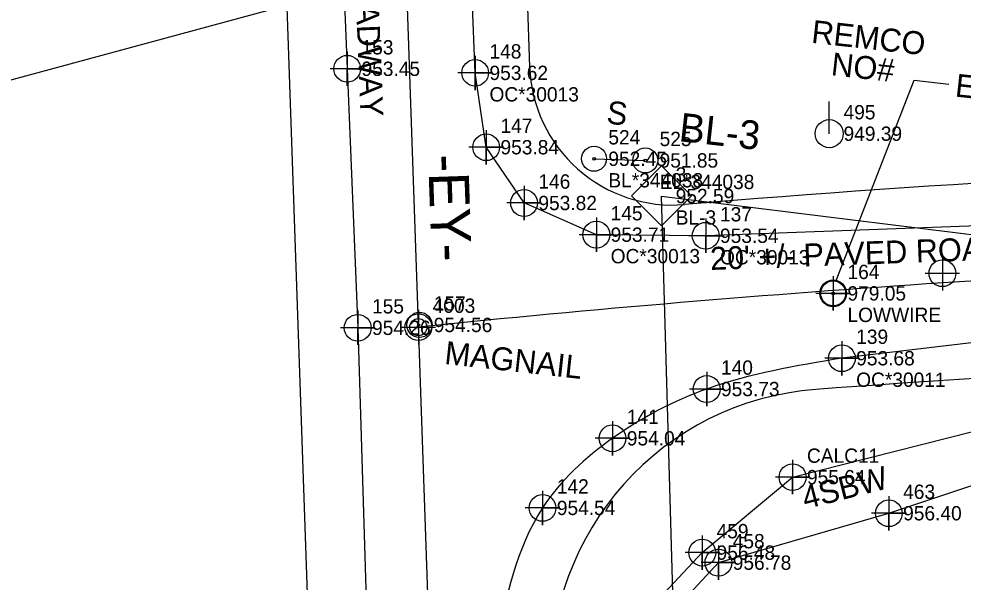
# Model space of a CAD drawing. Extents: x 1150279 to 1151282, y 654632 to 657999.
# Drawn here: x 1150502.6 to 1150667.5, y 657077.9 to 657176.2 of the extents above; entities that cross this region are included whole.
import ezdxf

# ---------------------------------------------------------------- set-up
doc = ezdxf.new("R2010")
doc.units = 0
for name, color, linetype in [('COGO Default Chain', 7, 'Continuous'), ('COGO Default Curve', 7, 'Continuous'), ('Cogo Default Point CELL', 7, 'Continuous'), ('COGO Default Point Number', 7, 'Continuous'), ('CTL Supplemental Horizontal and Vertical CELL', 7, 'Continuous'), ('CTL Supplemental Horizontal and Vertical Cogo Comment', 7, 'Continuous'), ('CTL Supplemental Horizontal and Vertical Cogo Elevation', 7, 'Continuous'), ('CTL Supplemental Horizontal and Vertical Cogo Number', 7, 'Continuous'), ('CTL Supplemental Horizontal and Vertical Text', 7, 'Continuous'), ('Default Symbol CELL', 7, 'Continuous'), ('Default Symbol Cogo Comment', 7, 'Continuous'), ('Default Symbol Cogo Elevation', 7, 'Continuous'), ('Default Symbol Cogo Number', 7, 'Continuous'), ('Exist Horizontal Alignment', 7, 'Continuous'), ('Exist Horizontal Alignment Direction Label', 7, 'Continuous'), ('Exist Horizontal Alignment Station Label', 7, 'Continuous'), ('Exist Other Culture Fence Line', 7, 'Continuous'), ('Exist Other Culture Fence Line Cogo Elevation', 7, 'Continuous'), ('Exist Other Culture Fence Line Cogo Number', 7, 'Continuous'), ('Exist Other Culture Fence Line Cogo Point CELL', 7, 'Continuous'), ('Exist Other Culture Fence Line Text', 7, 'Continuous'), ('Exist Other Culture Sign CELL', 7, 'Continuous'), ('Exist Other Culture Sign Cogo Comment', 7, 'Continuous'), ('Exist Other Culture Sign Cogo Elevation', 7, 'Continuous'), ('Exist Other Culture Sign Cogo Number', 7, 'Continuous'), ('Exist Other Culture Sign Text', 7, 'Continuous'), ('Exist Property Iron Pin CELL', 7, 'Continuous'), ('Exist Property Iron Pin Cogo Elevation', 7, 'Continuous'), ('Exist Property Iron Pin Cogo Number', 7, 'Continuous'), ('Exist Property Iron Pin Text', 7, 'Continuous'), ('Exist Property Line', 7, 'Continuous'), ('Exist Right of Way Line', 7, 'Continuous'), ('Exist Roads EOP', 7, 'Continuous'), ('Exist Roads EOP Cogo Comment', 7, 'Continuous'), ('Exist Roads EOP Cogo Elevation', 7, 'Continuous'), ('Exist Roads EOP Cogo Number', 7, 'Continuous'), ('Exist Roads EOP Cogo Point CELL', 7, 'Continuous'), ('Exist Roads EOP Text', 7, 'Continuous'), ('Exist Utilities Other Located Object CELL', 7, 'Continuous'), ('Exist Utilities Other Located Object Leader', 7, 'Continuous'), ('Exist Utilities Other Located Object Text', 7, 'Continuous'), ('Exist Utilities Power Pole CELL', 7, 'Continuous'), ('Exist Utilities Power Pole Cogo Elevation', 7, 'Continuous'), ('Exist Utilities Power Pole Cogo Number', 7, 'Continuous'), ('Exist Utilities Power Pole Text', 7, 'Continuous'), ('Old_Level_4', 7, 'Continuous')]:
    doc.layers.add(name, color=color, linetype=linetype)

msp = doc.modelspace()

# ---------------------------------------------------------------- linework, layer by layer
at = {"layer": 'COGO Default Chain'}
for p, q in [((1150568.54, 657231.15), (1150575.96, 657017.52)), ((1150663.4, 655450.47), (1150614.76, 657145.26)), ((1150614.76, 657145.26), (1150931.29, 657106.06))]:
    msp.add_line(p, q, dxfattribs=at)
msp.add_arc((1150828.33, 654635.5), 2500, 91.66254, 95.87761, dxfattribs=at)
at = {"layer": 'COGO Default Curve'}
msp.add_arc((1150828.33, 654635.5), 2500, 91.66254, 95.87761, dxfattribs=at)
at = {"layer": 'Cogo Default Point CELL'}
for points in [[(1150663.84, 657134.78), (1150663.84, 657131.78)], [(1150660.84, 657131.78), (1150663.84, 657131.78)], [(1150663.84, 657131.78), (1150666.84, 657131.78)], [(1150663.84, 657131.78), (1150663.84, 657128.78)], [(1150572.32, 657125.36), (1150572.32, 657122.36)], [(1150572.32, 657125.36), (1150572.32, 657122.36)], [(1150569.32, 657122.36), (1150572.32, 657122.36)], [(1150569.32, 657122.36), (1150572.32, 657122.36)], [(1150572.32, 657122.36), (1150575.32, 657122.36)], [(1150572.32, 657122.36), (1150572.32, 657119.36)], [(1150572.32, 657122.36), (1150575.32, 657122.36)], [(1150572.32, 657122.36), (1150572.32, 657119.36)]]:
    msp.add_lwpolyline(points, dxfattribs=at)
for centre in [(1150663.84, 657131.78), (1150572.32, 657122.36), (1150572.32, 657122.36)]:
    msp.add_circle(centre, 2.34, dxfattribs=at)
at = {"layer": 'CTL Supplemental Horizontal and Vertical CELL'}
msp.add_line((1150614.76, 657145.26), (1150614.76, 657145.26), dxfattribs=at)
msp.add_lwpolyline([(1150609.54, 657145.28), (1150614.78, 657150.52), (1150620.03, 657145.27), (1150614.79, 657140.03)], close=True, dxfattribs=at)
at = {"layer": 'Default Symbol CELL'}
msp.add_lwpolyline([(1150644.76, 657131.26), (1150644.76, 657125.26), (1150644.76, 657128.26), (1150647.76, 657128.26), (1150641.76, 657128.26)], dxfattribs=at)
msp.add_circle((1150644.76, 657128.26), 2.34, dxfattribs=at)
at = {"layer": 'Exist Horizontal Alignment'}
msp.add_line((1150568.54, 657231.15), (1150575.96, 657017.52), dxfattribs=at)
msp.add_arc((1150828.33, 654635.5), 2500, 91.66254, 95.87761, dxfattribs=at)
at = {"layer": 'Exist Horizontal Alignment Station Label'}
msp.add_circle((1150572.32, 657122.36), 1.5, dxfattribs=at)
at = {"layer": 'Exist Other Culture Fence Line'}
for points in [[(1150601.9, 657018.95), (1150605.15, 657042.83), (1150611.98, 657072.42), (1150621.9, 657083), (1150637.68, 657096.18), (1150678.11, 657106.44)], [(1150604.36, 657025.64), (1150606.72, 657040.79), (1150614.66, 657070.42), (1150624.72, 657081.25), (1150654.48, 657089.88), (1150677.88, 657097.66), (1150678.26, 657106.74)]]:
    msp.add_lwpolyline(points, dxfattribs=at)
at = {"layer": 'Exist Other Culture Fence Line Cogo Point CELL'}
for points in [[(1150637.68, 657099.18), (1150637.68, 657093.18), (1150637.68, 657096.18), (1150640.68, 657096.18), (1150634.68, 657096.18)], [(1150654.48, 657092.88), (1150654.48, 657086.88), (1150654.48, 657089.88), (1150657.48, 657089.88), (1150651.48, 657089.88)], [(1150621.9, 657086), (1150621.9, 657080), (1150621.9, 657083), (1150624.9, 657083), (1150618.9, 657083)], [(1150624.72, 657084.25), (1150624.72, 657078.25), (1150624.72, 657081.25), (1150627.72, 657081.25), (1150621.72, 657081.25)]]:
    msp.add_lwpolyline(points, dxfattribs=at)
for centre in [(1150637.68, 657096.18), (1150654.48, 657089.88), (1150621.9, 657083), (1150624.72, 657081.25)]:
    msp.add_circle(centre, 2.34, dxfattribs=at)
at = {"layer": 'Exist Other Culture Sign CELL'}
for centre, radius in [((1150603, 657151.76), 2.18), ((1150611.95, 657151.47), 2.18), ((1150603, 657151.76), 0.24), ((1150611.95, 657151.47), 0.24)]:
    msp.add_circle(centre, radius, dxfattribs=at)
at = {"layer": 'Exist Property Iron Pin CELL'}
for radius in [2.2, 0.0707]:
    msp.add_circle((1150572.51, 657122.75), radius, dxfattribs=at)
at = {"layer": 'Exist Property Line'}
msp.add_line((1150281.26, 657106.12), (1150549.35, 657178.59), dxfattribs=at)
at = {"layer": 'Exist Right of Way Line'}
for p, q in [((1150589.52, 657231.88), (1150591.75, 657167.81)), ((1150547.55, 657230.42), (1150554.98, 657016.79))]:
    msp.add_line(p, q, dxfattribs=at)
for centre, radius, start, end in [((1150616.74, 657168.68), 25, 181.9914, 274.7747), ((1150828.33, 654635.5), 2517, 91.66254, 94.77475), ((1150828.33, 654635.5), 2483, 91.66254, 94.31019), ((1150645.47, 657061.62), 50, 94.3102, 181.9914)]:
    msp.add_arc(centre, radius, start, end, dxfattribs=at)
at = {"layer": 'Exist Roads EOP'}
for p, q in [((1150582.24, 657166.76), (1150579.68, 657231.42)), ((1150622.5, 657138.32), (1150603.4, 657138.51))]:
    msp.add_line(p, q, dxfattribs=at)
for points in [[(1150555.6, 657230.84), (1150557.81, 657218.94), (1150559.89, 657167.47), (1150561.73, 657122.25), (1150563.33, 657070.95), (1150564.64, 657020.93), (1150563.6, 657016.73)], [(1150603.4, 657138.51), (1150590.78, 657144.04), (1150584.16, 657153.78), (1150582.24, 657166.76)], [(1150716.46, 657142.57), (1150671.62, 657140.1), (1150622.5, 657138.32)], [(1150717.08, 657124.05), (1150672.37, 657120.06), (1150646.28, 657116.94)]]:
    msp.add_lwpolyline(points, dxfattribs=at)
msp.add_spline([(1150646.28, 657116.94), (1150622.67, 657111.56), (1150606.22, 657102.96), (1150594, 657090.81), (1150585.84, 657066.56)], degree=3, dxfattribs=at)
at = {"layer": 'Exist Roads EOP Cogo Point CELL'}
for points in [[(1150559.89, 657170.47), (1150559.89, 657164.47), (1150559.89, 657167.47), (1150562.89, 657167.47), (1150556.89, 657167.47)], [(1150582.24, 657169.76), (1150582.24, 657163.76), (1150582.24, 657166.76), (1150585.24, 657166.76), (1150579.24, 657166.76)], [(1150584.16, 657156.78), (1150584.16, 657150.78), (1150584.16, 657153.78), (1150587.16, 657153.78), (1150581.16, 657153.78)], [(1150590.78, 657147.04), (1150590.78, 657141.04), (1150590.78, 657144.04), (1150593.78, 657144.04), (1150587.78, 657144.04)], [(1150603.4, 657141.51), (1150603.4, 657135.51), (1150603.4, 657138.51), (1150606.4, 657138.51), (1150600.4, 657138.51)], [(1150622.5, 657141.32), (1150622.5, 657135.32), (1150622.5, 657138.32), (1150625.5, 657138.32), (1150619.5, 657138.32)], [(1150561.73, 657125.25), (1150561.73, 657119.25), (1150561.73, 657122.25), (1150564.73, 657122.25), (1150558.73, 657122.25)], [(1150646.28, 657119.94), (1150646.28, 657113.94), (1150646.28, 657116.94), (1150649.28, 657116.94), (1150643.28, 657116.94)], [(1150622.67, 657114.56), (1150622.67, 657108.56), (1150622.67, 657111.56), (1150625.67, 657111.56), (1150619.67, 657111.56)], [(1150606.22, 657105.96), (1150606.22, 657099.96), (1150606.22, 657102.96), (1150609.22, 657102.96), (1150603.22, 657102.96)], [(1150594, 657093.81), (1150594, 657087.81), (1150594, 657090.81), (1150597, 657090.81), (1150591, 657090.81)]]:
    msp.add_lwpolyline(points, dxfattribs=at)
for centre in [(1150559.89, 657167.47), (1150582.24, 657166.76), (1150584.16, 657153.78), (1150590.78, 657144.04), (1150603.4, 657138.51), (1150622.5, 657138.32), (1150561.73, 657122.25), (1150646.28, 657116.94), (1150622.67, 657111.56), (1150606.22, 657102.96), (1150594, 657090.81)]:
    msp.add_circle(centre, 2.34, dxfattribs=at)
at = {"layer": 'Exist Utilities Other Located Object CELL'}
for radius in [2.18, 0.24]:
    msp.add_circle((1150644.76, 657128.26), radius, dxfattribs=at)
at = {"layer": 'Exist Utilities Other Located Object Leader'}
msp.add_lwpolyline([(1150645.27, 657130.5), (1150658.88, 657165.48), (1150664.98, 657164.8)], dxfattribs=at)
at = {"layer": 'Exist Utilities Power Pole CELL'}
for q in [(1150644.07, 657161.76), (1150644.07, 657156.14)]:
    msp.add_line((1150644.07, 657156.14), q, dxfattribs=at)
msp.add_circle((1150644.07, 657156.14), 2.45, dxfattribs=at)
at = {"layer": 'Old_Level_4'}
msp.add_line((1150603, 657151.76), (1150611.95, 657151.47), dxfattribs=at)

# ---------------------------------------------------------------- texts
at = {"layer": 'COGO Default Point Number'}
msp.add_text('4003', height=2.5, dxfattribs=at).set_placement((1150574.82, 657124.86))
at = {"layer": 'CTL Supplemental Horizontal and Vertical Cogo Comment'}
msp.add_text('BL-3', height=2.5, dxfattribs=at).set_placement((1150617.26, 657140.26))
at = {"layer": 'CTL Supplemental Horizontal and Vertical Cogo Elevation'}
msp.add_text('952.59', height=2.5, dxfattribs=at).set_placement((1150617.26, 657144.01))
at = {"layer": 'CTL Supplemental Horizontal and Vertical Cogo Number'}
msp.add_text('3', height=2.5, dxfattribs=at).set_placement((1150617.26, 657147.76))
at = {"layer": 'CTL Supplemental Horizontal and Vertical Text'}
msp.add_text('BL-3', height=5, rotation=353.6867, dxfattribs=at).set_placement((1150617.68, 657154.84))
at = {"layer": 'Default Symbol Cogo Comment'}
msp.add_text('LOWWIRE', height=2.5, dxfattribs=at).set_placement((1150647.26, 657123.26))
at = {"layer": 'Default Symbol Cogo Elevation'}
msp.add_text('979.05', height=2.5, dxfattribs=at).set_placement((1150647.26, 657127.01))
at = {"layer": 'Default Symbol Cogo Number'}
msp.add_text('164', height=2.5, dxfattribs=at).set_placement((1150647.26, 657130.76))
at = {"layer": 'Exist Horizontal Alignment Direction Label'}
msp.add_text('-EY-', height=7, rotation=271.9914, dxfattribs=at).set_placement((1150574.01, 657152.43))
at = {"layer": 'Exist Other Culture Fence Line Cogo Elevation'}
for s, p in [('955.64', (1150640.18, 657094.93)), ('956.40', (1150656.98, 657088.63)), ('956.48', (1150624.4, 657081.75)), ('956.78', (1150627.22, 657080))]:
    msp.add_text(s, height=2.5, dxfattribs=at).set_placement(p)
at = {"layer": 'Exist Other Culture Fence Line Cogo Number'}
for s, p in [('CALC11', (1150640.18, 657098.68)), ('463', (1150656.98, 657092.38)), ('459', (1150624.4, 657085.5)), ('458', (1150627.22, 657083.75))]:
    msp.add_text(s, height=2.5, dxfattribs=at).set_placement(p)
at = {"layer": 'Exist Other Culture Fence Line Text'}
msp.add_text('4SBW', height=4, rotation=14.2331, dxfattribs=at).set_placement((1150639.9, 657090.56))
at = {"layer": 'Exist Other Culture Sign Cogo Comment'}
for s, p in [('BL*344038', (1150605.5, 657146.76)), ('EL*344038', (1150614.45, 657146.47))]:
    msp.add_text(s, height=2.5, dxfattribs=at).set_placement(p)
at = {"layer": 'Exist Other Culture Sign Cogo Elevation'}
for s, p in [('952.45', (1150605.5, 657150.51)), ('951.85', (1150614.45, 657150.22))]:
    msp.add_text(s, height=2.5, dxfattribs=at).set_placement(p)
at = {"layer": 'Exist Other Culture Sign Cogo Number'}
for s, p in [('524', (1150605.5, 657154.26)), ('525', (1150614.45, 657153.97))]:
    msp.add_text(s, height=2.5, dxfattribs=at).set_placement(p)
at = {"layer": 'Exist Other Culture Sign Text'}
msp.add_text('S', height=4, rotation=353.6867, dxfattribs=at).set_placement((1150605.05, 657157.94))
at = {"layer": 'Exist Property Iron Pin Cogo Elevation'}
msp.add_text('954.56', height=2.5, dxfattribs=at).set_placement((1150575.01, 657121.5))
at = {"layer": 'Exist Property Iron Pin Cogo Number'}
msp.add_text('157', height=2.5, dxfattribs=at).set_placement((1150575.01, 657125.25))
at = {"layer": 'Exist Property Iron Pin Text'}
msp.add_text('MAGNAIL', height=4, rotation=353.6867, dxfattribs=at).set_placement((1150576.76, 657115.96))
at = {"layer": 'Exist Roads EOP Cogo Comment'}
for s, p in [('OC*30013', (1150584.74, 657161.76)), ('OC*30013', (1150605.9, 657133.51)), ('OC*30013', (1150625, 657133.32)), ('OC*30011', (1150648.78, 657111.94))]:
    msp.add_text(s, height=2.5, dxfattribs=at).set_placement(p)
at = {"layer": 'Exist Roads EOP Cogo Elevation'}
for s, p in [('953.45', (1150562.39, 657166.22)), ('953.62', (1150584.74, 657165.51)), ('953.84', (1150586.66, 657152.53)), ('953.82', (1150593.28, 657142.79)), ('953.71', (1150605.9, 657137.26)), ('953.54', (1150625, 657137.07)), ('954.26', (1150564.23, 657121)), ('953.68', (1150648.78, 657115.69)), ('953.73', (1150625.17, 657110.31)), ('954.04', (1150608.72, 657101.71)), ('954.54', (1150596.5, 657089.56))]:
    msp.add_text(s, height=2.5, dxfattribs=at).set_placement(p)
at = {"layer": 'Exist Roads EOP Cogo Number'}
for s, p in [('153', (1150562.39, 657169.97)), ('148', (1150584.74, 657169.26)), ('147', (1150586.66, 657156.28)), ('146', (1150593.28, 657146.54)), ('145', (1150605.9, 657141.01)), ('137', (1150625, 657140.82)), ('155', (1150564.23, 657124.75)), ('139', (1150648.78, 657119.44)), ('140', (1150625.17, 657114.06)), ('141', (1150608.72, 657105.46)), ('142', (1150596.5, 657093.31))]:
    msp.add_text(s, height=2.5, dxfattribs=at).set_placement(p)
at = {"layer": 'Exist Roads EOP Text'}
for s, rotation, p in [("22' PAVED ROADWAY", 272.3134, (1150559.98, 657214.72)), ("20' +/- PAVED ROADWAY", 2.0752, (1150623.33, 657132.34))]:
    msp.add_text(s, height=4, rotation=rotation, dxfattribs=at).set_placement(p)
at = {"layer": 'Exist Utilities Other Located Object Text'}
msp.add_text("ELEV = 979.05'", height=4, rotation=353.6867, dxfattribs=at).set_placement((1150665.93, 657162.64))
at = {"layer": 'Exist Utilities Power Pole Cogo Elevation'}
msp.add_text('949.39', height=2.5, dxfattribs=at).set_placement((1150646.57, 657154.89))
at = {"layer": 'Exist Utilities Power Pole Cogo Number'}
msp.add_text('495', height=2.5, dxfattribs=at).set_placement((1150646.57, 657158.64))
at = {"layer": 'Exist Utilities Power Pole Text'}
for s, p in [('REMCO', (1150640.84, 657172.02)), ('NO#', (1150644.27, 657166.36))]:
    msp.add_text(s, height=4, rotation=353.6867, dxfattribs=at).set_placement(p)

doc.saveas('drawing.dxf')
